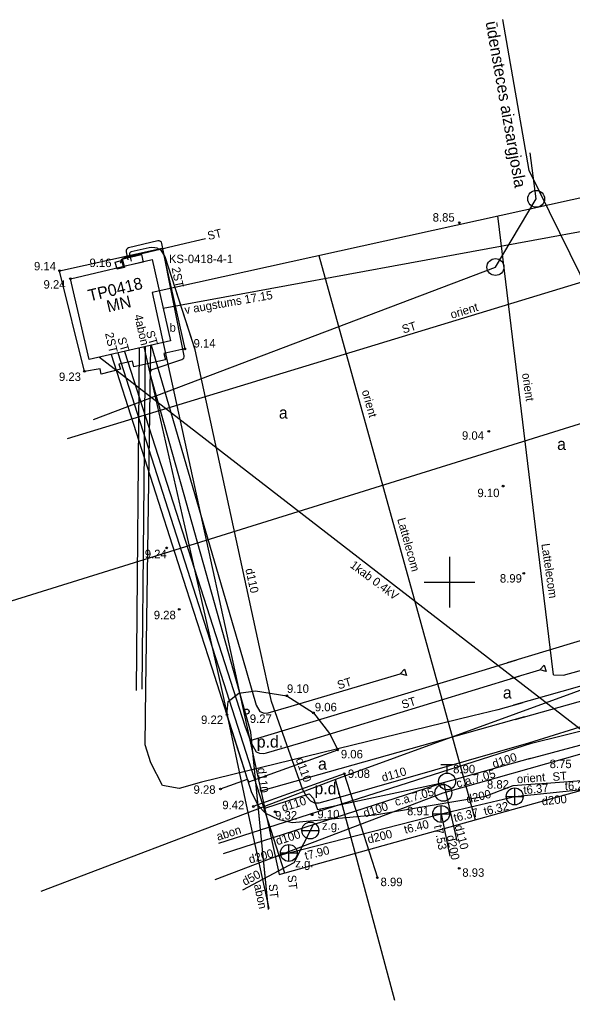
# Model space of a CAD drawing. Extents: x 496078 to 496285, y 304225 to 304369.
# Drawn here: x 496124.6 to 496157.3, y 304275.3 to 304333.3 of the extents above; entities that cross this region are included whole.
import ezdxf

# ---------------------------------------------------------------- set-up
doc = ezdxf.new("R2010")
doc.units = 0
for name, color, linetype in [('APGR_AIZS_####_####_#', 7, 'Continuous'), ('APGR_AIZS_####_TKST_#', 7, 'Continuous'), ('APGR_ELEM_####_####_#', 7, 'Continuous'), ('APGR_SARK_####_####_#', 7, 'Continuous'), ('APGS_VADP_ZSPR_####_#', 7, 'Continuous'), ('BUVE_BDET_####_####_#', 7, 'Continuous'), ('BUVE_BDET_####_TKST_#', 7, 'Continuous'), ('BUVE_EKAS_RAKS_TKST_#', 7, 'Continuous'), ('BUVE_ELEM_####_####_#', 7, 'Continuous'), ('CELI_CAPM_####_####_#', 7, 'Continuous'), ('CELI_CMAL_####_####_#', 7, 'Continuous'), ('CELI_CSEG_####_TKST_#', 7, 'Continuous'), ('ELEK_ACRL_####_####_#', 7, 'Continuous'), ('ELEK_ACRL_####_TKST_#', 7, 'Continuous'), ('ELEK_ELEM_####_####_#', 7, 'Continuous'), ('ELEK_ELEM_####_TKST_#', 7, 'Continuous'), ('ELEK_STTP_####_####_#', 7, 'Continuous'), ('ELEK_STTP_####_TKST_#', 7, 'Continuous'), ('ELEK_VADP_NEDR_####_#', 7, 'Continuous'), ('ELEK_VADP_NEDR_TKST_#', 7, 'Continuous'), ('ELEK_VADP_VSPR_####_#', 7, 'Continuous'), ('ELEK_VADP_VSPR_TKST_#', 7, 'Continuous'), ('ELEK_VADP_ZSPR_####_#', 7, 'Continuous'), ('ELEK_VADP_ZSPR_TKST_#', 7, 'Continuous'), ('ELEK_VADV_VSPR_####_#', 7, 'Continuous'), ('ELEK_VADV_VSPR_TKST_#', 7, 'Continuous'), ('ELEK_VADV_ZSPR_####_#', 7, 'Continuous'), ('ELEK_VADV_ZSPR_TKST_#', 7, 'Continuous'), ('GEOD_ELEM_####_####_#', 7, 'Continuous'), ('Level 21', 7, 'Continuous'), ('Level 24', 7, 'Continuous'), ('RAMI_UZMR_####_####_#', 7, 'Continuous'), ('RELJ_AATZ_####_TKST_#', 7, 'Continuous'), ('RELJ_ELEM_####_####_#', 7, 'Continuous'), ('SAKT_VADP_NEDR_####_#', 7, 'Continuous'), ('SAKT_VADP_NEDR_TKST_#', 7, 'Continuous'), ('SKAN_ELEM_####_####_#', 7, 'Continuous'), ('SKAN_ELEM_PAST_TKST_#', 7, 'Continuous'), ('SKAN_VADP_PAST_####_#', 7, 'Continuous'), ('SKAN_VADP_PAST_TKST_#', 7, 'Continuous'), ('TERT_IZMT_####_TKST_#', 7, 'Continuous'), ('UDTK_ELEM_####_####_#', 7, 'Continuous'), ('UDTK_ELEM_####_TKST_#', 7, 'Continuous'), ('UDTK_VADP_UDEN_####_#', 7, 'Continuous'), ('UDTK_VADP_UDEN_TKST_#', 7, 'Continuous')]:
    doc.layers.add(name, color=color, linetype=linetype)

msp = doc.modelspace()

# ---------------------------------------------------------------- linework, layer by layer
at = {"layer": 'APGR_AIZS_####_####_#'}
for points in [[(496154.713, 304324.372), (496153.144, 304333.305)], [(496171.482, 304276.481), (496169.303, 304289.245), (496168.626, 304293.523), (496167.995, 304297.351), (496154.713, 304324.372)]]:
    msp.add_lwpolyline(points, dxfattribs=at)
at = {"layer": 'APGR_ELEM_####_####_#'}
for centre in [(496155.12, 304322.7), (496152.71, 304318.66), (496149.63, 304287.54)]:
    msp.add_circle(centre, 0.5, dxfattribs=at)
at = {"layer": 'APGR_SARK_####_####_#'}
for p, q in [((496155.118, 304322.698), (496154.758, 304325.421)), ((496152.707, 304318.659), (496155.118, 304322.698)), ((496128.948, 304309.635), (496152.707, 304318.659)), ((496149.627, 304287.537), (496157.839, 304289.874)), ((496136.138, 304282.414), (496149.627, 304287.537))]:
    msp.add_line(p, q, dxfattribs=at)
at = {"layer": 'APGS_VADP_ZSPR_####_#'}
for p, q in [((496153.427, 304295.248), (496167.718, 304299.606)), ((496152.113, 304294.847), (496153.98, 304295.416)), ((496138.196, 304290.636), (496152.113, 304294.847))]:
    msp.add_line(p, q, dxfattribs=at)
at = {"layer": 'BUVE_BDET_####_####_#'}
for points in [[(496126.934, 304318.445), (496132.993, 304319.787), (496134.339, 304313.818), (496133.093, 304313.541), (496133.205, 304313.174), (496131.319, 304312.754)], [(496131.319, 304312.754), (496131.239, 304313.09), (496130.443, 304312.916), (496130.528, 304312.614), (496129.385, 304312.325), (496129.328, 304312.644), (496128.405, 304312.484), (496126.934, 304318.445)]]:
    msp.add_lwpolyline(points, dxfattribs=at)
at = {"layer": 'BUVE_ELEM_####_####_#'}
msp.add_circle((496137.998, 304292.35), 0.148, dxfattribs=at)
at = {"layer": 'CELI_CAPM_####_####_#'}
msp.add_line((496143.766, 304288.669), (496138.391, 304286.732), dxfattribs=at)
for points in [[(496136.447, 304287.771), (496138.051, 304288.34), (496136.832, 304292.16), (496136.911, 304292.943), (496137.526, 304293.447), (496138.519, 304293.581), (496140.37, 304293.287), (496141.948, 304292.273), (496142.9, 304291.046), (496143.396, 304290.086)], [(496138.047, 304288.339), (496138.122, 304288.201), (496143.396, 304290.086)]]:
    msp.add_lwpolyline(points, dxfattribs=at)
at = {"layer": 'CELI_CMAL_####_####_#'}
msp.add_line((496143.766, 304288.669), (496145.728, 304282.517), dxfattribs=at)
at = {"layer": 'ELEK_ACRL_####_####_#'}
for p, q in [((496138.823, 304295.898), (496134.952, 304313.757)), ((496139.464, 304292.942), (496138.823, 304295.898)), ((496154.662, 304290.482), (496143.543, 304287.279)), ((496139.219, 304281.41), (496138.364, 304289.955)), ((496141.324, 304287.714), (496140.586, 304289.777))]:
    msp.add_line(p, q, dxfattribs=at)
at = {"layer": 'ELEK_ELEM_####_####_#'}
for points in [[(496130.767, 304318.633), (496130.332, 304318.528), (496130.229, 304318.955), (496130.664, 304319.06)], [(496130.605, 304319.125), (496131.774, 304319.394), (496131.875, 304318.955), (496130.706, 304318.686)]]:
    msp.add_lwpolyline(points, close=True, dxfattribs=at)
for points in [[(496147.444, 304294.48), (496147.083, 304294.589), (496147.339, 304294.866)], [(496147.339, 304294.866), (496147.444, 304294.48)], [(496155.703, 304294.719), (496155.342, 304294.828), (496155.598, 304295.105)], [(496155.598, 304295.105), (496155.703, 304294.719)]]:
    msp.add_lwpolyline(points, dxfattribs=at)
at = {"layer": 'ELEK_STTP_####_####_#'}
msp.add_lwpolyline([(496127.577, 304317.971), (496132.41, 304319.105), (496133.491, 304314.299), (496128.686, 304313.193), (496127.577, 304317.971)], dxfattribs=at)
at = {"layer": 'ELEK_VADP_NEDR_####_#'}
for p, q in [((496132.357, 304314.038), (496137.747, 304295.537)), ((496130.768, 304313.655), (496136.701, 304295.186)), ((496137.747, 304295.537), (496138.565, 304292.729)), ((496136.701, 304295.186), (496137.881, 304291.513)), ((496153.622, 304294.302), (496155.342, 304294.828)), ((496140.629, 304292.667), (496147.083, 304294.589)), ((496141.204, 304290.506), (496154.113, 304294.452)), ((496138.565, 304292.729), (496138.771, 304292.347)), ((496138.771, 304292.347), (496139.035, 304292.257)), ((496139.279, 304292.28), (496140.629, 304292.667)), ((496139.035, 304292.257), (496139.279, 304292.28)), ((496137.881, 304291.513), (496138.271, 304290.495)), ((496138.271, 304290.495), (496138.556, 304289.967)), ((496139.173, 304289.911), (496141.204, 304290.506)), ((496138.556, 304289.967), (496138.762, 304289.893)), ((496138.762, 304289.893), (496139.014, 304289.874)), ((496139.014, 304289.874), (496139.173, 304289.911))]:
    msp.add_line(p, q, dxfattribs=at)
at = {"layer": 'ELEK_VADP_VSPR_####_#'}
msp.add_lwpolyline([(496127.411, 304308.505), (496164.51, 304319.823), (496167.892, 304320.979), (496176.431, 304322.113), (496181.231, 304322.724), (496191.596, 304323.927)], dxfattribs=at)
at = {"layer": 'ELEK_VADP_ZSPR_####_#'}
for p, q in [((496132.743, 304320.207), (496131.017, 304319.793)), ((496135.572, 304320.324), (496134.049, 304319.966)), ((496134.049, 304319.966), (496130.714, 304319.181)), ((496132.226, 304319.791), (496131.17, 304319.559)), ((496132.396, 304319.815), (496132.226, 304319.791)), ((496132.566, 304319.805), (496132.396, 304319.815)), ((496132.715, 304319.768), (496132.566, 304319.805)), ((496132.836, 304319.699), (496132.715, 304319.768)), ((496132.958, 304319.611), (496132.836, 304319.699)), ((496133.046, 304319.496), (496132.958, 304319.611)), ((496134.296, 304313.412), (496132.986, 304320.051)), ((496130.528, 304318.882), (496130.714, 304319.181)), ((496130.869, 304319.554), (496130.977, 304319.08)), ((496131.095, 304319.504), (496131.072, 304319.456)), ((496131.072, 304319.456), (496131.073, 304319.407)), ((496131.073, 304319.407), (496131.162, 304319)), ((496131.126, 304319.539), (496131.095, 304319.504)), ((496131.17, 304319.559), (496131.126, 304319.539)), ((496133.179, 304319.256), (496133.046, 304319.496)), ((496134.828, 304314.14), (496133.179, 304319.256)), ((496134.952, 304313.757), (496133.179, 304319.256)), ((496131.48, 304293.603), (496131.653, 304313.876)), ((496131.997, 304313.955), (496131.794, 304293.678)), ((496131.912, 304313.936), (496134.28, 304303.514)), ((496132.044, 304293.737), (496132.336, 304314.033)), ((496129.99, 304313.493), (496134.425, 304299.642)), ((496130.381, 304313.584), (496136.313, 304295.055)), ((496138.823, 304295.898), (496134.952, 304313.757)), ((496132.417, 304312.588), (496134.164, 304313.184)), ((496134.28, 304303.514), (496136.209, 304295.02)), ((496134.425, 304299.642), (496135.937, 304294.929)), ((496139.464, 304292.942), (496138.823, 304295.898)), ((496135.937, 304294.929), (496137.42, 304290.31)), ((496136.209, 304295.02), (496136.655, 304293.056)), ((496136.313, 304295.055), (496140.237, 304282.8)), ((496159.906, 304294.464), (496153.785, 304292.72)), ((496164.614, 304293.595), (496154.662, 304290.482)), ((496136.655, 304293.056), (496137.978, 304286.823)), ((496140.586, 304289.777), (496139.464, 304292.942)), ((496154.331, 304292.875), (496152.842, 304292.451)), ((496152.842, 304292.451), (496151.382, 304292.095)), ((496154.843, 304290.483), (496163.624, 304292.643)), ((496136.344, 304284.555), (496154.843, 304290.483)), ((496137.42, 304290.31), (496138.293, 304287.56)), ((496154.662, 304290.482), (496143.543, 304287.279)), ((496141.324, 304287.714), (496140.586, 304289.777)), ((496155.19, 304288.074), (496160.572, 304288.474)), ((496141.558, 304287.295), (496141.324, 304287.714)), ((496152.126, 304287.337), (496153.75, 304287.967)), ((496153.75, 304287.967), (496155.318, 304288.084)), ((496138.293, 304287.56), (496138.479, 304287.185)), ((496138.479, 304287.185), (496138.664, 304286.809)), ((496141.791, 304287.048), (496141.558, 304287.295)), ((496143.543, 304287.279), (496142.259, 304286.934)), ((496145.572, 304286.246), (496152.126, 304287.337)), ((496137.978, 304286.823), (496139.3, 304280.687)), ((496138.664, 304286.809), (496139.102, 304286.334)), ((496142.025, 304286.928), (496141.791, 304287.048)), ((496142.259, 304286.934), (496142.025, 304286.928)), ((496139.102, 304286.334), (496139.863, 304285.991)), ((496139.863, 304285.991), (496140.681, 304285.782)), ((496140.681, 304285.782), (496145.572, 304286.246))]:
    msp.add_line(p, q, dxfattribs=at)
for points in [[(496139.296, 304280.635), (496138.248, 304291.124), (496132.289, 304312.345)], [(496151.382, 304292.095), (496135.332, 304288.179), (496134.007, 304287.788), (496133.026, 304287.984), (496132.339, 304289.309), (496131.996, 304290.389), (496132.044, 304293.737)]]:
    msp.add_lwpolyline(points, dxfattribs=at)
for centre, start, end in [((496132.79, 304320.012), 11.15926, 103.48337), ((496131.064, 304319.598), 103.48337, 192.8685), ((496134.1, 304313.373), 288.82567, 11.15926), ((496132.482, 304312.399), 108.82567, 195.68346)]:
    msp.add_arc(centre, 0.2, start, end, dxfattribs=at)
at = {"layer": 'ELEK_VADV_VSPR_####_#'}
msp.add_line((496180.524, 304324.939), (496133.06, 304316.215), dxfattribs=at)
at = {"layer": 'ELEK_VADV_ZSPR_####_#'}
msp.add_line((496129.299, 304313.334), (496161.188, 304288.645), dxfattribs=at)
at = {"layer": 'GEOD_ELEM_####_####_#'}
for p, q in [((496150, 304301.5), (496150, 304300)), ((496148.5, 304300), (496150, 304300)), ((496150, 304300), (496150, 304298.5)), ((496150, 304300), (496151.5, 304300))]:
    msp.add_line(p, q, dxfattribs=at)
at = {"layer": 'Level 21'}
msp.add_lwpolyline([(496164.622, 304311.533), (496119.806, 304297.572)], dxfattribs=at)
at = {"layer": 'Level 24'}
for points in [[(496167.995, 304297.351), (496143.254, 304288.326)], [(496143.254, 304288.326), (496125.831, 304281.709)], [(496146.763, 304275.256), (496143.254, 304288.326)]]:
    msp.add_lwpolyline(points, dxfattribs=at)
at = {"layer": 'RAMI_UZMR_####_####_#'}
for p, q in [((496181.881, 304328.088), (496132.418, 304317.16)), ((496132.418, 304317.16), (496139.922, 304282.712)), ((496139.922, 304282.712), (496195.979, 304298.352))]:
    msp.add_line(p, q, dxfattribs=at)
at = {"layer": 'RELJ_ELEM_####_####_#'}
for centre in [(496150.574, 304321.281), (496126.934, 304318.445), (496127.577, 304317.971), (496134.339, 304313.818), (496128.405, 304312.484), (496152.313, 304308.939), (496153.161, 304305.695), (496133.271, 304302.04), (496154.386, 304300.535), (496134.008, 304298.398), (496140.37, 304293.287), (496141.948, 304292.273), (496136.832, 304292.16), (496143.382, 304290.081), (496143.77, 304288.67), (496136.447, 304287.771), (496138.391, 304286.732), (496139.68, 304286.42), (496141.867, 304286.24), (496150.565, 304283.072), (496145.728, 304282.517)]:
    msp.add_circle(centre, 0.05, dxfattribs=at)
at = {"layer": 'SAKT_VADP_NEDR_####_#'}
for p, q in [((496152.863, 304321.539), (496152.847, 304321.673)), ((496155.236, 304301.979), (496152.863, 304321.539)), ((496142.268, 304319.336), (496147.88, 304299.081)), ((496156.14, 304294.53), (496155.236, 304301.979)), ((496156.74, 304294.499), (496174.76, 304299.582)), ((496147.88, 304299.081), (496151.518, 304285.947)), ((496153.87, 304291.887), (496161.985, 304294.172)), ((496156.14, 304294.53), (496156.74, 304294.499)), ((496138.845, 304287.656), (496154.446, 304292.049))]:
    msp.add_line(p, q, dxfattribs=at)
at = {"layer": 'SKAN_ELEM_####_####_#'}
for p, q in [((496153.848, 304286.827), (496153.848, 304287.827)), ((496153.348, 304287.327), (496154.348, 304287.327)), ((496149.501, 304285.791), (496149.501, 304286.791)), ((496149.001, 304286.291), (496150.001, 304286.291)), ((496140.493, 304283.481), (496140.493, 304284.481)), ((496139.993, 304283.981), (496140.993, 304283.981))]:
    msp.add_line(p, q, dxfattribs=at)
for centre in [(496153.848, 304287.327), (496149.501, 304286.291), (496140.493, 304283.981)]:
    msp.add_circle(centre, 0.5, dxfattribs=at)
at = {"layer": 'SKAN_VADP_PAST_####_#'}
for p, q in [((496153.848, 304287.327), (496159.104, 304287.866)), ((496149.501, 304286.291), (496153.848, 304287.327)), ((496140.493, 304283.981), (496149.501, 304286.291)), ((496149.501, 304286.291), (496150.003, 304283.798)), ((496140.493, 304283.981), (496139.695, 304283.753))]:
    msp.add_line(p, q, dxfattribs=at)
at = {"layer": 'UDTK_ELEM_####_####_#'}
for p, q in [((496149.474, 304289.214), (496150.224, 304289.214)), ((496149.849, 304288.714), (496149.849, 304289.214)), ((496141.262, 304285.309), (496142.262, 304285.309))]:
    msp.add_line(p, q, dxfattribs=at)
for centre in [(496149.849, 304288.214), (496141.762, 304285.309)]:
    msp.add_circle(centre, 0.5, dxfattribs=at)
at = {"layer": 'UDTK_VADP_UDEN_####_#'}
for p, q in [((496154.678, 304289.554), (496173.247, 304294.572)), ((496149.641, 304288.15), (496154.787, 304289.584)), ((496136.633, 304283.956), (496149.783, 304288.19)), ((496142.196, 304286.558), (496149.639, 304288.159)), ((496139.067, 304286.64), (496141.693, 304287.472)), ((496141.693, 304287.472), (496141.949, 304287.199)), ((496141.949, 304287.199), (496142.196, 304286.558)), ((496140.798, 304283.423), (496141.943, 304285.666)), ((496137.771, 304281.793), (496140.798, 304283.423))]:
    msp.add_line(p, q, dxfattribs=at)
msp.add_lwpolyline([(496149.641, 304288.15), (496150.417, 304284.708)], dxfattribs=at)

# ---------------------------------------------------------------- texts
at = {"layer": 'APGR_AIZS_####_TKST_#'}
msp.add_text('ūdensteces aizsargjosla', height=0.7, rotation=279.96666, dxfattribs=at).set_placement((496152.122, 304333.151))
at = {"layer": 'BUVE_BDET_####_TKST_#'}
msp.add_text('b', height=0.5, dxfattribs=at).set_placement((496133.437, 304314.83))
at = {"layer": 'BUVE_EKAS_RAKS_TKST_#'}
msp.add_text('MN', height=0.7, rotation=13.09742, dxfattribs=at).set_placement((496129.805, 304315.976))
at = {"layer": 'CELI_CSEG_####_TKST_#'}
for p in [(496139.901, 304309.692), (496156.356, 304307.834), (496153.151, 304293.126), (496142.218, 304288.911)]:
    msp.add_text('a', height=0.7, dxfattribs=at).set_placement(p)
at = {"layer": 'ELEK_ACRL_####_TKST_#'}
for rotation, p in [(282.2306, (496137.919, 304300.776)), (289.68373, (496140.888, 304289.519)), (275.71391, (496138.639, 304289.002)), (16.06986, (496146.058, 304288.188))]:
    msp.add_text('d110', height=0.5, rotation=rotation, dxfattribs=at).set_placement(p)
at = {"layer": 'ELEK_ELEM_####_TKST_#'}
msp.add_text('KS-0418-4-1', height=0.5, dxfattribs=at).set_placement((496133.401, 304318.893))
at = {"layer": 'ELEK_STTP_####_TKST_#'}
msp.add_text('TP0418', height=0.7, rotation=13.58199, dxfattribs=at).set_placement((496128.712, 304316.618))
at = {"layer": 'ELEK_VADP_NEDR_TKST_#'}
for rotation, p in [(286.24154, (496130.348, 304314.435)), (286.24154, (496132.033, 304314.821)), (16.58352, (496143.437, 304293.66)), (16.99844, (496147.24, 304292.508))]:
    msp.add_text('ST', height=0.5, rotation=rotation, dxfattribs=at).set_placement(p)
at = {"layer": 'ELEK_VADP_VSPR_TKST_#'}
for s, p in [('orient', (496150.13, 304315.593)), ('ST', (496147.266, 304314.719))]:
    msp.add_text(s, height=0.5, rotation=16.96455, dxfattribs=at).set_placement(p)
at = {"layer": 'ELEK_VADP_ZSPR_TKST_#'}
for s, rotation, p in [('ST', 13.24196, (496135.74, 304320.254)), ('2ST', 281.16215, (496133.558, 304318.605)), ('4abon', 282.7974, (496131.342, 304315.796)), ('2ST', 282.7974, (496129.622, 304314.731)), ('orient', 4.24436, (496153.995, 304288.104)), ('ST', 4.24436, (496156.103, 304288.241)), ('abon', 17.76968, (496136.302, 304284.698)), ('ST', 275.71391, (496140.414, 304282.658)), ('abon', 282.15947, (496138.423, 304282.089)), ('ST', 275.71391, (496139.298, 304282.13))]:
    msp.add_text(s, height=0.5, rotation=rotation, dxfattribs=at).set_placement(p)
at = {"layer": 'ELEK_VADV_VSPR_TKST_#'}
msp.add_text('v augstums 17.15', height=0.5, rotation=9.86387, dxfattribs=at).set_placement((496134.364, 304315.874))
at = {"layer": 'ELEK_VADV_ZSPR_TKST_#'}
msp.add_text('1kab 0.4kV', height=0.5, rotation=323.19922, dxfattribs=at).set_placement((496144.068, 304300.927))
at = {"layer": 'RELJ_AATZ_####_TKST_#'}
for s, p in [(' 8.85', (496148.812, 304321.349)), ('9.16', (496128.704, 304318.66)), (' 9.14', (496125.234, 304318.463)), (' 9.24', (496125.799, 304317.382)), (' 9.14', (496134.671, 304313.896)), (' 9.23', (496126.711, 304311.917)), (' 9.04', (496150.544, 304308.439)), (' 9.10', (496151.459, 304305.043)), (' 9.24', (496131.788, 304301.429)), (' 8.99', (496152.786, 304299.984)), (' 9.28', (496132.319, 304297.815)), (' 9.10', (496140.194, 304293.459)), (' 9.06', (496141.843, 304292.367)), (' 9.22', (496135.116, 304291.616)), (' 9.27', (496137.998, 304291.679)), (' 9.06', (496143.382, 304289.581)), (' 8.75', (496155.729, 304289.003)), (' 9.08', (496143.8, 304288.422)), (' 9.28', (496134.67, 304287.484)), (' 9.42', (496136.372, 304286.573)), (' 9.10', (496141.994, 304286.032)), (' 9.32', (496139.494, 304285.962)), (' 8.93', (496150.565, 304282.572)), (' 8.99', (496145.728, 304282.017))]:
    msp.add_text(s, height=0.5, dxfattribs=at).set_placement(p)
at = {"layer": 'SAKT_VADP_NEDR_TKST_#'}
for s, rotation, p in [('orient', 278.29815, (496154.275, 304312.35)), ('orient', 285.48488, (496144.8, 304311.321)), ('Lattelecom', 285.48488, (496146.895, 304303.743)), ('Lattelecom', 278.29815, (496155.422, 304302.265))]:
    msp.add_text(s, height=0.5, rotation=rotation, dxfattribs=at).set_placement(p)
at = {"layer": 'SKAN_ELEM_PAST_TKST_#'}
for s, p in [('8.82', (496152.208, 304287.789)), ('8.91', (496147.483, 304286.211)), ('z.g.', (496140.871, 304283.126))]:
    msp.add_text(s, height=0.5, dxfattribs=at).set_placement(p)
at = {"layer": 'SKAN_VADP_PAST_TKST_#'}
for s, rotation, p in [('t6.23', 2.42354, (496156.823, 304287.694)), ('d200', 13.63265, (496151.048, 304286.906)), ('t6.37', 5.56966, (496154.389, 304287.451)), ('d200', 5.56966, (496155.469, 304286.799)), ('t6.37', 13.63265, (496150.303, 304285.808)), ('t6.32', 13.63265, (496152.087, 304286.195)), ('t6.40', 14.1291, (496147.375, 304285.109)), ('d200', 14.1291, (496145.209, 304284.533)), ('t7.53', 280.73368, (496149.073, 304285.591)), ('d200', 281.68313, (496149.814, 304284.987)), ('d200', 15.7936, (496138.197, 304283.346)), ('t7.90', 14.1291, (496141.494, 304283.563))]:
    msp.add_text(s, height=0.5, rotation=rotation, dxfattribs=at).set_placement(p)
at = {"layer": 'TERT_IZMT_####_TKST_#'}
for p in [(496138.594, 304290.22), (496142.009, 304287.455)]:
    msp.add_text('p.d.', height=0.7, dxfattribs=at).set_placement(p)
at = {"layer": 'UDTK_ELEM_####_TKST_#'}
for s, p in [('8.90', (496150.208, 304288.698)), ('z.g.', (496142.451, 304285.358))]:
    msp.add_text(s, height=0.5, dxfattribs=at).set_placement(p)
at = {"layer": 'UDTK_VADP_UDEN_TKST_#'}
for s, rotation, p in [('d100', 17.74086, (496152.611, 304289.002)), ('c.a.7.05', 15.56653, (496150.468, 304287.833)), ('c.a.7.05', 15.56653, (496146.828, 304286.755)), ('d110', 17.74086, (496140.152, 304286.411)), ('d100', 17.74086, (496144.99, 304286.079)), ('d100', 17.74086, (496139.81, 304284.431)), ('d110', 284.49547, (496150.285, 304285.585)), ('d50', 28.30126, (496137.893, 304282.031))]:
    msp.add_text(s, height=0.5, rotation=rotation, dxfattribs=at).set_placement(p)

doc.saveas('drawing.dxf')
